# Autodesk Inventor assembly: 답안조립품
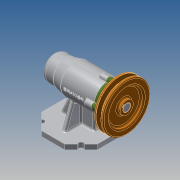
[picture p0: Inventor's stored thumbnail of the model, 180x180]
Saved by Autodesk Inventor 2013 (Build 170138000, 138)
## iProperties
Created: 2019-12
Part Number: 답안조립품
Document SubType Name: Assembly
Designer: Administrator
Author: Administrator
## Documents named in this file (12)
- C:\Users\Administrator\Desktop\491204V1001\답안조립품.iam
- C:\Users\Administrator\Desktop\491204V1001\본체.ipt
- C:\Users\Administrator\Desktop\491204V1001\V벨트풀리.ipt
- C:\Users\Administrator\Desktop\491204V1001\멈춤나사 M3.ipt
- C:\Users\Administrator\Desktop\491204V1001\베어링 6004.ipt
- C:\Users\Administrator\Desktop\491204V1001\베어링 51202.ipt
- C:\Users\Administrator\Desktop\491204V1001\볼트 M4.ipt
- C:\Users\Administrator\Desktop\491204V1001\어댑터슬리브.ipt
- C:\Users\Administrator\Desktop\491204V1001\오일 실.ipt
- C:\Users\Administrator\Desktop\491204V1001\축.ipt
- C:\Users\Administrator\Desktop\491204V1001\커버.ipt
- C:\Users\Administrator\Desktop\491204V1001\키 5 x 5 x 16.ipt
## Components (1 placed, 1 different names)
1. V벨트풀리:1 — 각도:3
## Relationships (1: Angle 1)
- 각도:3 [Angle]: V벨트풀리:1
